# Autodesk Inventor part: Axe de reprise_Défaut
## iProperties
Shininess: 64.0
Length Units: 11269
Angle Units: 11279
Time Units: 11290
Mass Units: 11283
Length Display Precision: 3
Angle Display Precision: 2
Compacted: True
Part Number: Axe de reprise_Défaut
Document SubType Name: Modeling
Created: 2006-01
Material: Par défaut
Designer: riri
Density: 0.0
Volumn: 0.0
Area: 0.0
PropertySet Name: Model Information
Control State: 0
Master: False
Checked Out: False
Author: riri
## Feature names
1. Base1
